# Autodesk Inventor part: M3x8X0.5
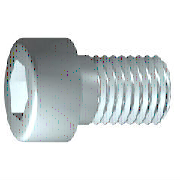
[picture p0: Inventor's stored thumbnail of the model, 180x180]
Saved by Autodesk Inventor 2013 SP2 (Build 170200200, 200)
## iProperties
IsCustomPart: 1
Created: 2009-02
Part Number: M3x8X0.5
Material: 강, 연강
Description: 6각머리 태핑 나사
Document SubType Name: Modeling
Standard: KS B 1003
Designer: SeoGD™[esajin.kr]
Standards Organization: KS
Language: ko-KR
Size Designation: M 3 x 8
Categories: <MemberInstance><Categories><Category DisplayName="조임쇠" InternalName="e4da775c-781d-43d5-af7c-5136215cf5a6" Mnemonic="FSTN"><Category DisplayName="볼트" InternalN
Density: 1 g/cm^3
Author: SeoGD™[esajin.kr]
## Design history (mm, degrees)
sketch "스케치1"
  geometry: L1 (-0.867, 0)-(8, 0); L2 (8, 0)-(8, 1.5); L3 (8, 1.5)-(1.25, 1.5); L4 (1.25, 1.5)-(0.943, 1.5); L5 (0.943, 1.5)-(0, 1.5); L6 (0, 1.5)-(0, 2.75); L7 (0, 2.75)-(-3, 2.75); L8 (-3, 2.75)-(-3, 1.443); L9 (-3, 1.443)-(-1.7, 1.443); L10 (-1.7, 1.443)-(-0.867, 0); L11 (-5.2, 0)-(10.2, 0) reference; L12 (0, -0.55)-(0, 3.3) reference; L13 (1.25, 1.5)-(0, 1.5)
  constraints: 22 end point, 6 parallel, 2 collinear, 2 perpendicular, 1 horizontal, 1 point on line
  dimensions: "d1" = 6.75 distance from line of L3.end L2 (= GEL); "d2" = 0.30683 distance of L4.end L3.end (computed from GAL); "d3" = 3 distance between parallel lines of L8 L6 (= KOH); "d4" = 1.3 distance of L8.end L9.end (= INTI); "d5" = 60 deg angle of L10 L1; "d6" = 3 diameter of L3 L1 (= GD); "d7" = 3 diameter of L5 L1 (= BDM); "d8" = 2.88675 diameter of L9 L1 (= 1.1547 x SW); "d9" = 5.5 diameter of L7 L1 (= KOD); "d26" = 8 distance between parallel lines of L12 L2 (= NLG)
revolve "본체" sketch "스케치1" stored, may be unused: angle "d10" = 90 deg
sketch "스케치2"
  geometry: L1 (0, -3.85)-(0, 3.85) reference; L2 (-3.85, 0)-(3.85, 0) reference; L3 (1.443, 0)-(0.722, -1.25); L4 (0.722, -1.25)-(-0.722, -1.25); L5 (-0.722, -1.25)-(-1.443, 0); L6 (-1.443, 0)-(-0.722, 1.25); L7 (-0.722, 1.25)-(0.722, 1.25); L8 (0.722, 1.25)-(1.443, 0); 2 further points
  constraints: 12 end point, 1 coincident, 1 horizontal alignment, 1 point on line, 12 other
extrude "슬롯" join sketch "스케치2" stored distance "d11" = 10; taper "d12" = 0 deg
workplane "Work Plane1"
fillet "Fillet2" dims "d30" = 0.1 (= R)
body "Solid1"
fillet "모깎기1" dims "d17" = 0.3 (= RR)
feature "스레드" dims "d13" = 6.75 (= GEL), "d14" = 0
chamfer "모따기1" distance "d15" = 0.30673 (= -0.5 x SPD + 0.5 x GD); stored, may be unused: second distance "d16" = 0.30673 (= GUL), angle "d27" = 45 deg
other parameters: "GD" = 3 (= NND) [user parameter; used in 2 equation terms], "NLG" = 8 [user parameter; used in 1 equation term], "GEL" = 6.75 [user parameter; used in 2 equation terms], "KOD" = 5.5 [user parameter; used in 1 equation term], "KOH" = 3 [user parameter; used in 1 equation term], "INTI" = 1.3 [user parameter; used in 1 equation term], "GAL" = 0.30673 (= 0.61345 x PTC) [user parameter; used in 1 equation term], "GUL" = 0.30673 (= 0.61345 x PTC) [user parameter; used in 1 equation term], "BDM" = 3 (= NND) [user parameter; used in 1 equation term], "SW" = 2.5 [user parameter; used in 2 equation terms], "RR" = 0.3 [user parameter; used in 1 equation term], "SPD" = 2.38655 (= NND - 1.2269 x PTC) [user parameter; used in 1 equation term], "d19" = 0, "d28" = 0, "d29" = 0, "R" = 0.1 [user parameter; used in 1 equation term], "PHH" = 0.1 [user parameter], "GD1" = 2.38655 (= THREADDIA - 1.2269 x PTC) [user parameter], "THREADDIA" = 3 [user parameter; used in 1 equation term], "FAWI" = 45 deg [user parameter], "PTC" = 0.5 [user parameter; used in 5 equation terms], "NND" = 3 [user parameter; used in 3 equation terms], "TOA" = 30 deg [user parameter], "E0" = 2.8875 (= 1.155 x SW) [user parameter]
